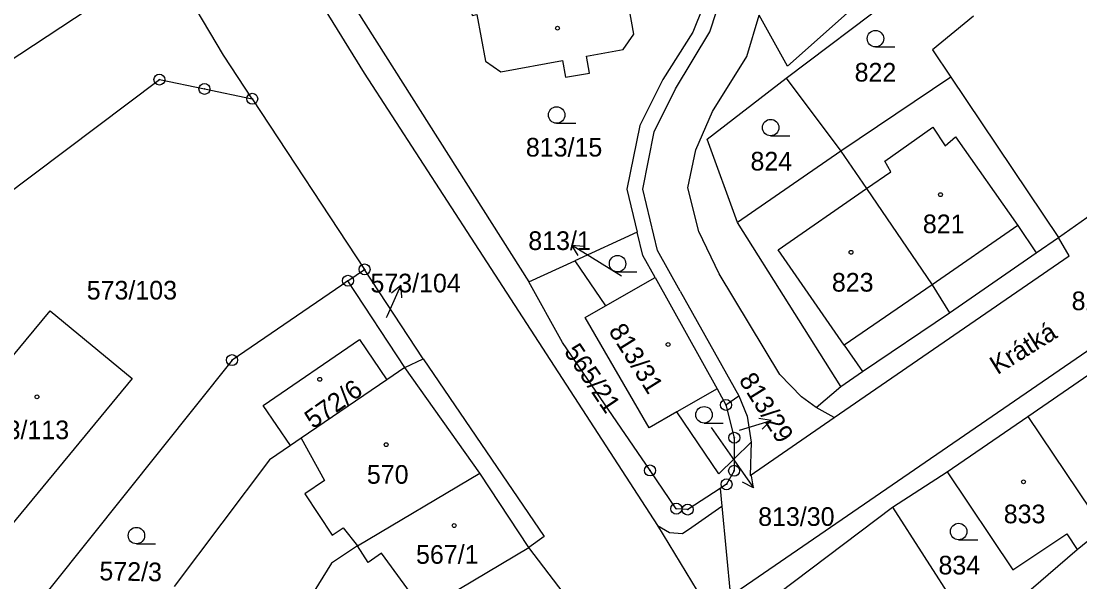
# Model space of a CAD drawing. Extents: x -776606 to -776076, y -974328 to -973875.
# Drawn here: x -776367.5 to -776271.1, y -973997.7 to -973946.7 of the extents above; entities that cross this region are included whole.
import ezdxf

# ---------------------------------------------------------------- set-up
doc = ezdxf.new("R2010")
doc.units = 0
for name, color, linetype in [('Hranice parcel', 7, 'Continuous'), ('Parcelní čísla', 7, 'Continuous'), ('Pop  PČ popisy', 7, 'Continuous'), ('Vnitřní kresba', 7, 'Continuous'), ('Značky bodu BP', 7, 'Continuous'), ('Značky budov', 7, 'Continuous'), ('Značky kultur', 7, 'Continuous')]:
    doc.layers.add(name, color=color, linetype=linetype)

msp = doc.modelspace()

# ---------------------------------------------------------------- linework, layer by layer
at = {"layer": 'Hranice parcel'}
for p, q in [((-776297.88, -973951.84), (-776284.08, -973941.43)), ((-776338.75, -973942.85), (-776321.28, -973970.41)), ((-776273.08, -973966.36), (-776248.44, -973948.9)), ((-776297.88, -973951.84), (-776292.9, -973958.5)), ((-776282.89, -973951.76), (-776292.9, -973958.5)), ((-776282.89, -973951.76), (-776273.08, -973966.36)), ((-776346.46, -973953.73), (-776336.24, -973969.27)), ((-776292.9, -973958.5), (-776302.3, -973965)), ((-776292.91, -973979.92), (-776302.3, -973965)), ((-776311.42, -973965.87), (-776317.09, -973968.48)), ((-776321.28, -973970.41), (-776317.09, -973968.48)), ((-776317.09, -973968.48), (-776314.32, -973972.59)), ((-776337.75, -973970.3), (-776336.24, -973969.27)), ((-776332.57, -973978.19), (-776337.75, -973970.3)), ((-776318.24, -973975.91), (-776321.28, -973970.41)), ((-776314.32, -973972.59), (-776309.8, -973970.01)), ((-776309.8, -973970.01), (-776304.16, -973980.15)), ((-776275.87, -973982.65), (-776267.49, -973976.87)), ((-776332.57, -973978.19), (-776334.21, -973979.31)), ((-776325.75, -973987.82), (-776332.57, -973978.19)), ((-776295.13, -973981.83), (-776292.91, -973979.92)), ((-776304.16, -973980.15), (-776307.81, -973982.25)), ((-776304.16, -973980.15), (-776303.35, -973981.61)), ((-776283.21, -973987.69), (-776275.87, -973982.65)), ((-776301.05, -973985), (-776302.6, -973986.53)), ((-776302.6, -973986.53), (-776302.61, -973987.61)), ((-776288.2, -973990.91), (-776283.21, -973987.69)), ((-776336.89, -973994.45), (-776325.75, -973987.82)), ((-776321.3, -973994.6), (-776325.75, -973987.82)), ((-776302.67, -974001.86), (-776288.2, -973990.91)), ((-776288.2, -973990.91), (-776280.61, -974002.73)), ((-776271.38, -973994.77), (-776268.9, -973992.75)), ((-776330.9, -974000.3), (-776321.3, -973994.6)), ((-776280.61, -974002.73), (-776271.38, -973994.77))]:
    msp.add_line(p, q, dxfattribs=at)
for points in [[(-776313.98, -973911.05), (-776297.73, -973912.06), (-776288.32, -973927.36), (-776286.35, -973940.59), (-776297.76, -973950.76), (-776300.32, -973946.11)], [(-776348.8, -973929.48), (-776343.01, -973940.47), (-776336.28, -973951.4), (-776326.2, -973966.93), (-776309.58, -973992.58), (-776304.42, -974001.08), (-776303.62, -974003.12), (-776297.56, -974011.17), (-776288.84, -974021.6), (-776272.77, -974040.55), (-776267.29, -974044.95), (-776253.84, -974055.49), (-776252.47, -974056.28)], [(-776357.89, -973934.92), (-776360.16, -973944.78), (-776376.25, -973955.36)], [(-776346.46, -973953.73), (-776349.07, -973949.75), (-776357.89, -973934.92)], [(-776327.4, -973940.82), (-776326.45, -973946.13), (-776326.01, -973946.05), (-776325.24, -973950.29), (-776323.84, -973951.26), (-776318.22, -973950.24), (-776317.95, -973951.77), (-776315.78, -973951.38), (-776316.05, -973949.85), (-776312.7, -973949.24), (-776311.73, -973947.84), (-776312.5, -973943.6), (-776311.81, -973943.48), (-776304.89, -973942.24)], [(-776304.89, -973942.24), (-776305.41, -973945.33), (-776306.38, -973947.66), (-776309.08, -973951.97), (-776311.19, -973956.17), (-776312.36, -973961.96), (-776311.42, -973965.87)], [(-776295.13, -973981.83), (-776296.49, -973980.88), (-776298.45, -973978.83), (-776303.97, -973969.66), (-776305.82, -973965.81), (-776306.81, -973961.85), (-776306.08, -973958.37), (-776304.57, -973954.89), (-776301.44, -973949.87), (-776300.32, -973946.11)], [(-776280.81, -973946.19), (-776284.56, -973949.27), (-776282.89, -973951.76)], [(-776374.94, -973977.27), (-776378.47, -973974.07), (-776377.87, -973969.26), (-776354.91, -973951.98), (-776350.81, -973952.83), (-776346.46, -973953.73)], [(-776302.3, -973965), (-776305.05, -973957.4), (-776297.88, -973951.84)], [(-776292.9, -973958.5), (-776290.55, -973961.91), (-776284.59, -973970.68), (-776283.02, -973973.23)], [(-776309.8, -973970.01), (-776310.91, -973967.99), (-776311.42, -973965.87)], [(-776283.02, -973973.23), (-776275.12, -973967.75), (-776273.08, -973966.36)], [(-776332.57, -973978.19), (-776330.9, -973977.4), (-776336.24, -973969.27)], [(-776337.75, -973970.3), (-776338.32, -973970.69), (-776348.3, -973977.53), (-776374.53, -974010.37)], [(-776376.01, -973990.03), (-776377.33, -973988.94), (-776377.56, -973986.47), (-776376.48, -973985.17), (-776374.78, -973985), (-776364.86, -973973.04), (-776357.39, -973979.21), (-776369.37, -973993.74), (-776374.09, -973989.85), (-776376.01, -973990.03)], [(-776307.81, -973982.25), (-776310.35, -973983.7), (-776316.15, -973973.64), (-776314.32, -973972.59)], [(-776292.91, -973979.92), (-776290.92, -973978.58), (-776283.02, -973973.23)], [(-776342.98, -973985.31), (-776345.48, -973981.66), (-776336.71, -973975.66), (-776334.21, -973979.31)], [(-776303.87, -973989.21), (-776306.83, -973991.14), (-776307.87, -973991.06), (-776310.26, -973987.58), (-776318.24, -973975.91)], [(-776334.21, -973979.31), (-776342, -973984.63), (-776342.98, -973985.31)], [(-776303.35, -973981.61), (-776302.17, -973980.77), (-776301.41, -973982.63), (-776301.05, -973985)], [(-776303.35, -973981.61), (-776302.59, -973984.6), (-776302.6, -973986.53)], [(-776301.05, -973985), (-776301.15, -973988.05), (-776293.49, -973982.77), (-776295.13, -973981.83)], [(-776302.6, -973986.53), (-776304, -973987.9), (-776307.81, -973982.25)], [(-776275.87, -973982.65), (-776270.15, -973991.2), (-776268.9, -973992.75)], [(-776342.98, -973985.31), (-776344.9, -973986.62), (-776353.58, -973998.16)], [(-776302.61, -973987.61), (-776303.3, -973988.84), (-776303.87, -973989.21)], [(-776283.21, -973987.69), (-776277.23, -973996.63), (-776272.33, -973993.35), (-776271.38, -973994.77)], [(-776303.87, -973989.21), (-776303.72, -973990.83), (-776302.93, -973999.08), (-776302.67, -974001.86)], [(-776336.89, -973994.45), (-776339.24, -973996.03), (-776344.63, -974004.7)], [(-776330.9, -974000.3), (-776334.7, -973995.1), (-776335.9, -973995.95), (-776336.89, -973994.45)], [(-776317.7, -973999.3), (-776318.56, -973998.17), (-776321.3, -973994.6)]]:
    msp.add_lwpolyline(points, dxfattribs=at)
at = {"layer": 'Pop  PČ popisy'}
for p, q in [((-776314.86, -973968.64), (-776317.405, -973967.05)), ((-776317.405, -973967.05), (-776316.29, -973967.156)), ((-776317.405, -973967.05), (-776316.821, -973968.005)), ((-776312.87, -973969.89), (-776314.86, -973968.64)), ((-776334.16, -973973.47), (-776332.939, -973970.728)), ((-776332.939, -973970.728), (-776333.804, -973971.44)), ((-776332.939, -973970.728), (-776332.889, -973971.847)), ((-776334.25, -973973.66), (-776334.16, -973973.47)), ((-776299.24, -973983.043), (-776300.344, -973982.857)), ((-776304.71, -973983.67), (-776302.57, -973986.71)), ((-776302.11, -973983.92), (-776302.12, -973983.92)), ((-776302.11, -973983.92), (-776299.24, -973983.043)), ((-776299.24, -973983.043), (-776300.051, -973983.814)), ((-776302.57, -973986.71), (-776300.849, -973989.168)), ((-776300.849, -973989.168), (-776301.833, -973988.635)), ((-776300.849, -973989.168), (-776301.013, -973988.061))]:
    msp.add_line(p, q, dxfattribs=at)
at = {"layer": 'Vnitřní kresba'}
for p, q in [((-776304.82, -973947.64), (-776304.21, -973945.77)), ((-776307.95, -973952.83), (-776304.82, -973947.64)), ((-776309.89, -973956.74), (-776307.95, -973952.83)), ((-776310.93, -973961.96), (-776309.89, -973956.74)), ((-776288.9, -973959.4), (-776284.53, -973956.3)), ((-776284.53, -973956.3), (-776283.4, -973958)), ((-776283.4, -973958), (-776282.45, -973957.2)), ((-776282.45, -973957.2), (-776276.79, -973965.28)), ((-776288.34, -973960.39), (-776288.9, -973959.4)), ((-776290.55, -973961.91), (-776288.34, -973960.39)), ((-776309.58, -973967.56), (-776310.93, -973961.96)), ((-776298.6, -973967.47), (-776290.55, -973961.91)), ((-776276.79, -973965.28), (-776284.59, -973970.68)), ((-776276.79, -973965.28), (-776275.12, -973967.75)), ((-776272.13, -973968.03), (-776273.08, -973966.36)), ((-776307.52, -973971.26), (-776309.58, -973967.56)), ((-776292.58, -973976.18), (-776298.6, -973967.47)), ((-776293.49, -973982.77), (-776272.13, -973968.03)), ((-776302.45, -973998.67), (-776260.07, -973969.53)), ((-776307.52, -973971.26), (-776302.17, -973980.77)), ((-776284.59, -973970.68), (-776292.58, -973976.18)), ((-776292.58, -973976.18), (-776290.92, -973978.58)), ((-776330.9, -973977.4), (-776319.9, -973993.6)), ((-776342, -973984.63), (-776339.89, -973988.49)), ((-776339.89, -973988.49), (-776341.67, -973989.72)), ((-776341.67, -973989.72), (-776339.18, -973993.46)), ((-776339.18, -973993.46), (-776338.18, -973992.79)), ((-776338.18, -973992.79), (-776336.89, -973994.45)), ((-776319.9, -973993.6), (-776321.3, -973994.6))]:
    msp.add_line(p, q, dxfattribs=at)
msp.add_lwpolyline([(-776309.58, -973992.58), (-776308.49, -973993.22), (-776307.31, -973993.31), (-776306.47, -973992.73), (-776303.72, -973990.83)], dxfattribs=at)
at = {"layer": 'Značky bodu BP'}
for centre, radius in [((-776354.91, -973951.98), 0.5), ((-776354.91, -973951.98), 0.0303), ((-776350.81, -973952.83), 0.5), ((-776350.81, -973952.83), 0.0303), ((-776346.46, -973953.73), 0.5), ((-776346.46, -973953.73), 0.0303), ((-776336.24, -973969.27), 0.5), ((-776336.24, -973969.27), 0.0303), ((-776337.75, -973970.3), 0.5), ((-776337.75, -973970.3), 0.0303), ((-776348.3, -973977.53), 0.5), ((-776348.3, -973977.53), 0.0303), ((-776303.35, -973981.61), 0.5), ((-776303.35, -973981.61), 0.0303), ((-776302.59, -973984.6), 0.5), ((-776302.59, -973984.6), 0.0303), ((-776310.26, -973987.58), 0.5), ((-776310.26, -973987.58), 0.0303), ((-776302.61, -973987.61), 0.5), ((-776302.61, -973987.61), 0.0303), ((-776303.3, -973988.84), 0.5), ((-776303.3, -973988.84), 0.0303), ((-776307.87, -973991.06), 0.5), ((-776306.83, -973991.14), 0.5), ((-776307.87, -973991.06), 0.0303), ((-776306.83, -973991.14), 0.0303)]:
    msp.add_circle(centre, radius, dxfattribs=at)
at = {"layer": 'Značky budov'}
for centre in [(-776318.677, -973947.299), (-776283.827, -973962.459), (-776291.967, -973967.709), (-776308.617, -973976.109), (-776340.317, -973979.279), (-776366.057, -973980.869), (-776334.277, -973985.229), (-776276.267, -973988.619), (-776328.087, -973992.599)]:
    msp.add_circle(centre, 0.175, dxfattribs=at)
at = {"layer": 'Značky kultur'}
for p, q in [((-776289.743, -973949), (-776287.993, -973949)), ((-776318.763, -973955.95), (-776317.013, -973955.95)), ((-776299.283, -973957.1), (-776297.533, -973957.1)), ((-776313.213, -973969.5), (-776311.463, -973969.5)), ((-776305.343, -973983.26), (-776303.593, -973983.26)), ((-776357.003, -973994.26), (-776355.253, -973994.26)), ((-776282.173, -973993.89), (-776280.423, -973993.89))]:
    msp.add_line(p, q, dxfattribs=at)
for centre in [(-776289.743, -973948.25), (-776318.763, -973955.2), (-776299.283, -973956.35), (-776313.213, -973968.75), (-776305.343, -973982.51), (-776282.173, -973993.14), (-776357.003, -973993.51)]:
    msp.add_circle(centre, 0.75, dxfattribs=at)

# ---------------------------------------------------------------- texts
at = {"layer": 'Parcelní čísla'}
for s, p in [('822', (-776291.64, -973952.16)), ('813/15', (-776321.56, -973958.99)), ('824', (-776301.12, -973960.26)), ('821', (-776285.43, -973965.97)), ('813/1', (-776321.338, -973967.5)), ('573/103', (-776361.526, -973972.01)), ('573/104', (-776335.706, -973971.36)), ('823', (-776293.71, -973971.29)), ('825', (-776271.89, -973972.98)), ('573/113', (-776371.346, -973984.73)), ('570', (-776336.03, -973988.79)), ('833', (-776278.07, -973992.39)), ('813/30', (-776300.42, -973992.628)), ('567/1', (-776331.558, -973996.08)), ('834', (-776284.01, -973997.05))]:
    msp.add_text(s, height=1.7, dxfattribs=at).set_placement(p)
for s, rotation, p in [('813/31', 302, (-776314.082, -973974.862)), ('565/21', 304, (-776318.142, -973976.752)), ('813/29', 302, (-776302.232, -973979.342)), ('572/6', 35, (-776340.932, -973983.836)), ('572/3', 359, (-776360.384, -973997.579))]:
    msp.add_text(s, height=1.7, rotation=rotation, dxfattribs=at).set_placement(p)
at = {"layer": 'Pop  PČ popisy'}
msp.add_text('Krátká', height=1.7, rotation=32, dxfattribs=at).set_placement((-776278.649, -973978.9))

doc.saveas('drawing.dxf')
